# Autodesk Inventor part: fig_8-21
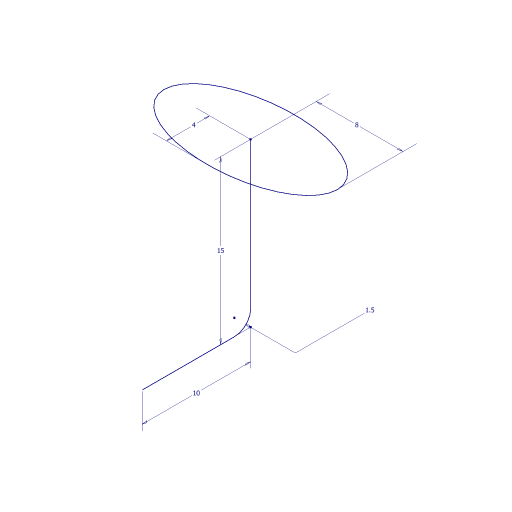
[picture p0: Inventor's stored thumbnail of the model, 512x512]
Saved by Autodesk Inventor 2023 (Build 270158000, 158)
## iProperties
Created: 2013-07
Part Number: fig_8-21
Material: Generic
Document SubType Name: Modeling
Designer: CADCIM
Density: 1 g/cm^3
Appearance: Default
Author: CADCIM
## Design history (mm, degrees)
sketch "Sketch1" dims "d0" = 8, "d1" = 4
  geometry: 2 further points; 1 other entity
  constraints: 1 coincident, 2 other
sketch "Sketch2"
  geometry: L1 (0, 0)-(0, -13.5); L2 (-1.5, -15)-(-10, -15); A1 r 1.5 centre (-1.5, -13.5) between (-1.5, -15) and (0, -13.5); 1 further point
  constraints: 4 end point, 2 point on circle, 2 point on line, 2 tangent, 1 centre point, 1 perpendicular, 1 vertical
  dimensions: "d2" = 15 distance of L1.start point (0, -15); "d3" = 10 distance of point (0, -15) L2.end; "d4" = 1.5 radius of A1
